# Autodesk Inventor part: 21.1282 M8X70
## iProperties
Created: 2006-02
Part Number: 21.1282 M8X70
Material: Steel, Mild
Description: Cylinder Head Cap Screw
Document SubType Name: Modeling
Standard: DIN 7984
Designer: Andy Moles
Standards Organization: DIN
Language: en-US
Size Designation: M8 x 60
Categories: <MemberInstance><Categories><Category DisplayName="Fasteners" InternalName="e4da775c-781d-43d5-af7c-5136215cf5a6" Mnemonic="FSTN"><Category DisplayName="Bolts"
Mass: 32.0174 g
Surface Area: 22.7431 cm^2
Volume: 4.07346 cm^3
Density: 7.86 g/cm^3
Author: Andy Moles
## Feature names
1. Body [Revolution]
2. Slot [Extrusion]
3. Fillet1
4. Chamfer1
